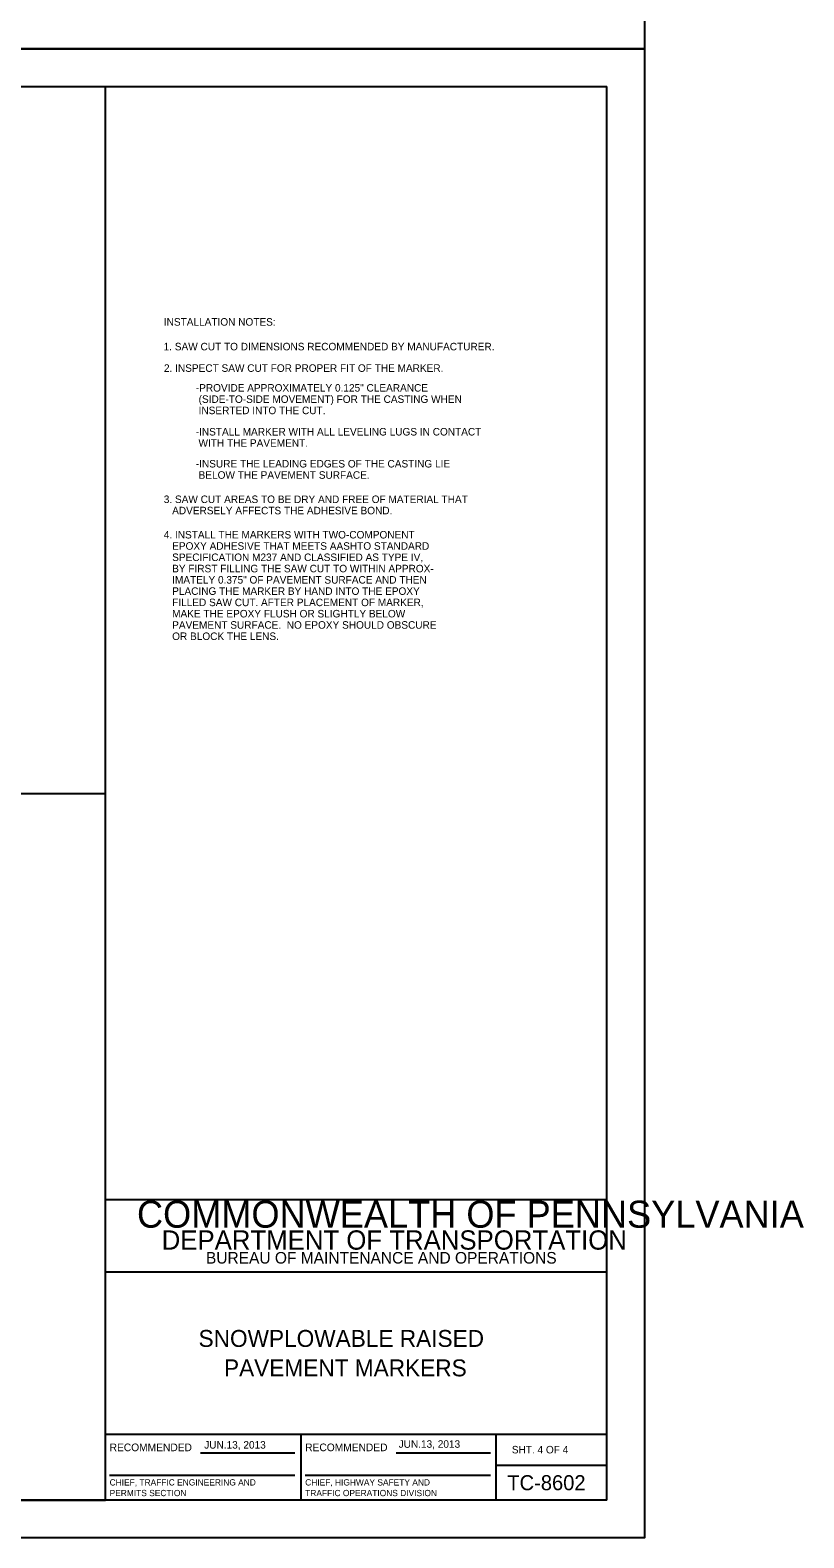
# Model space of a CAD drawing. Extents: x 639362 to 641108, y 298458 to 299646.
# Drawn here: x 640799 to 641108, y 298458 to 299059 of the extents above; entities that cross this region are included whole.
import ezdxf

# ---------------------------------------------------------------- set-up
doc = ezdxf.new("R2010")
doc.units = 0
for name, color, linetype in [('1', 7, 'Continuous'), ('2', 7, 'Continuous'), ('Level 1', 7, 'Continuous'), ('PLT-BNDY', 7, 'Continuous')]:
    doc.layers.add(name, color=color, linetype=linetype)

msp = doc.modelspace()

# ---------------------------------------------------------------- linework, layer by layer
at = {"layer": '1'}
for p, q in [((640243.31, 299036.63), (641029.31, 299036.63)), ((640829.31, 298592.63), (640829.31, 299036.63)), ((641029.31, 298472.63), (641029.31, 299036.63)), ((640243.31, 298754.63), (640829.31, 298754.63)), ((640829.31, 298472.63), (640829.31, 298592.63)), ((640829.31, 298592.63), (641029.31, 298592.63)), ((641029.31, 298563.63), (640829.31, 298563.63)), ((640829.31, 298499), (641029.31, 298499)), ((640907.31, 298499), (640907.31, 298472.63)), ((640985.19, 298472.63), (640985.19, 298499)), ((640867.24, 298491.57), (640904.87, 298491.57)), ((640945.24, 298491.57), (640982.87, 298491.57)), ((640985.19, 298486.63), (641029.31, 298486.63)), ((641029.31, 298472.63), (640243.31, 298472.63)), ((640243.31, 298472.63), (640829.31, 298472.63))]:
    msp.add_line(p, q, dxfattribs=at)
at = {"layer": 'Level 1'}
for p, q in [((640830.99, 298482.68), (640904.87, 298482.68)), ((640908.99, 298482.68), (640982.87, 298482.68))]:
    msp.add_line(p, q, dxfattribs=at)
at = {"layer": 'PLT-BNDY'}
for points in [[(640203.31, 299645.63), (641044.31, 299645.63), (641044.31, 299051.63), (640203.31, 299051.63)], [(640203.31, 299051.63), (641044.31, 299051.63), (641044.31, 298457.63), (640203.31, 298457.63)]]:
    msp.add_lwpolyline(points, close=True, dxfattribs=at)

# ---------------------------------------------------------------- texts
at = {"layer": '1'}
for s, height, p in [('COMMONWEALTH OF PENNSYLVANIA', 10.7828, (640841.9, 298581.36)), ('DEPARTMENT OF TRANSPORTATION', 7.6837, (640851.76, 298572.61)), ('BUREAU OF MAINTENANCE AND OPERATIONS', 4.6253, (640869.41, 298567.04)), ('SNOWPLOWABLE RAISED', 6.75, (640866.46, 298533.81)), ('PAVEMENT MARKERS', 6.75, (640876.61, 298522.06)), ('RECOMMENDED', 3.048, (640830.99, 298492.2)), ('JUN.13, 2013', 3, (640868.73, 298493.23)), ('RECOMMENDED', 3.048, (640908.99, 298492.2)), ('JUN.13, 2013', 3, (640946.26, 298493.56)), ('SHT. 4 OF 4', 3, (640991.4, 298491.31)), ('TC-8602', 6, (640989.6, 298476.63))]:
    msp.add_text(s, height=height, dxfattribs=at).set_placement(p)
at = {"layer": '2'}
for s, p in [('INSTALLATION NOTES:', (640852.62, 298941.23)), ('1. SAW CUT TO DIMENSIONS RECOMMENDED BY MANUFACTURER.', (640852.53, 298931.39)), ('2. INSPECT SAW CUT FOR PROPER FIT OF THE MARKER.', (640852.67, 298922.81)), ('-PROVIDE APPROXIMATELY 0.125" CLEARANCE', (640865.37, 298914.92)), (' (SIDE-TO-SIDE MOVEMENT) FOR THE CASTING WHEN', (640865.37, 298910.42)), (' INSERTED INTO THE CUT.', (640865.37, 298905.92)), ('-INSTALL MARKER WITH ALL LEVELING LUGS IN CONTACT', (640865.33, 298897.41)), (' WITH THE PAVEMENT.', (640865.33, 298892.91)), ('-INSURE THE LEADING EDGES OF THE CASTING LIE ', (640865.37, 298884.65)), (' BELOW THE PAVEMENT SURFACE.', (640865.37, 298880.15)), ('3. SAW CUT AREAS TO BE DRY AND FREE OF MATERIAL THAT', (640852.59, 298870.47)), ('   ADVERSELY AFFECTS THE ADHESIVE BOND.', (640852.59, 298865.97)), ('4. INSTALL THE MARKERS WITH TWO-COMPONENT', (640852.59, 298856.33)), ('   SPECIFICATION M237 AND CLASSIFIED AS TYPE IV,', (640852.59, 298847.33)), ('   EPOXY ADHESIVE THAT MEETS AASHTO STANDARD', (640852.59, 298851.83)), ('   BY FIRST FILLING THE SAW CUT TO WITHIN APPROX-', (640852.59, 298842.83)), ('   IMATELY 0.375" OF PAVEMENT SURFACE AND THEN', (640852.59, 298838.33)), ('   PLACING THE MARKER BY HAND INTO THE EPOXY', (640852.59, 298833.83)), ('   FILLED SAW CUT. AFTER PLACEMENT OF MARKER, ', (640852.59, 298829.33)), ('   MAKE THE EPOXY FLUSH OR SLIGHTLY BELOW', (640852.59, 298824.83)), ('   PAVEMENT SURFACE.  NO EPOXY SHOULD OBSCURE', (640852.59, 298820.33)), ('   OR BLOCK THE LENS.', (640852.59, 298815.83))]:
    msp.add_text(s, height=3, dxfattribs=at).set_placement(p)
at = {"layer": 'Level 1'}
for s, p in [('CHIEF, TRAFFIC ENGINEERING AND', (640830.99, 298478.51)), ('PERMITS SECTION', (640830.99, 298474.26)), ('TRAFFIC OPERATIONS DIVISION', (640908.99, 298474.26)), ('CHIEF, HIGHWAY SAFETY AND', (640908.99, 298478.51))]:
    msp.add_text(s, height=2.5, dxfattribs=at).set_placement(p)

doc.saveas('drawing.dxf')
